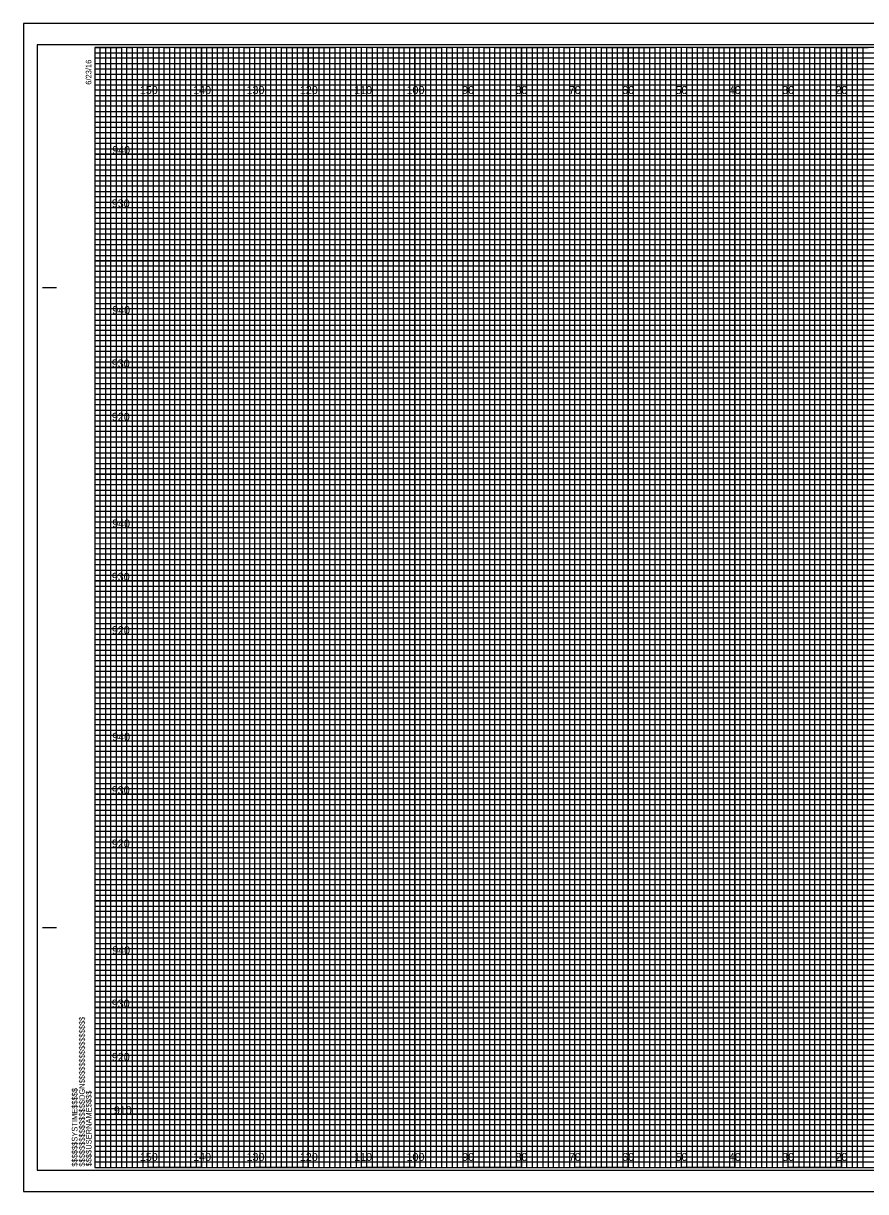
# Model space of a CAD drawing. Extents: x -13 to 323, y -4 to 214.
# Drawn here: x -13.4 to 144.5, y -4.5 to 214.5 of the extents above; entities that cross this region are included whole.
import ezdxf

# ---------------------------------------------------------------- set-up
doc = ezdxf.new("R2010")
doc.units = 0
for name, color, linetype in [('Prop XS Elevation Labels', 7, 'Continuous'), ('Prop XS Offset Labels', 7, 'Continuous'), ('Sheet Cross Section CELL', 7, 'Continuous'), ('Sheet Cross Section Grid Major CELL', 7, 'Continuous'), ('Sheet Cross Section Grid Middle CELL', 7, 'Continuous'), ('Sheet Cross Section Grid Minor 1 CELL', 7, 'Continuous'), ('Sheet Cross Section Grid Minor 2 CELL', 7, 'Continuous'), ('Sheet Cutting Line CELL', 7, 'Continuous'), ('Sheet DOT Grid CELL', 7, 'Continuous'), ('Sheet Plot Border Inside CELL', 7, 'Continuous'), ('Sheet Plot Border Outside CELL', 7, 'Continuous')]:
    doc.layers.add(name, color=color, linetype=linetype)

msp = doc.modelspace()

# ---------------------------------------------------------------- linework, layer by layer
at = {"layer": 'Sheet Cross Section CELL'}
for p, q in [((-9.8, 165), (-7.3, 165)), ((-9.7, 165), (-7.2, 165)), ((-9.8, 45), (-7.3, 45)), ((-9.7, 45), (-7.2, 45)), ((0, 0), (0, 0)), ((0, 0), (0, 0)), ((0, 0), (0, 0)), ((0, 0), (0, 0)), ((0, 0), (0, 0)), ((0, 0), (0, 0)), ((0, 0), (0, 0))]:
    msp.add_line(p, q, dxfattribs=at)
msp.add_lwpolyline([(320, 210), (0, 210), (0, 0), (320, 0)], close=True, dxfattribs=at)
at = {"layer": 'Sheet Cross Section Grid Major CELL'}
for p, q in [((10, 210), (0, 210)), ((10, 0), (10, 210)), ((30, 210), (20, 210)), ((20, 210), (20, 0)), ((30, 0), (30, 210)), ((50, 210), (40, 210)), ((40, 210), (40, 0)), ((50, 0), (50, 210)), ((70, 210), (60, 210)), ((60, 210), (60, 0)), ((70, 0), (70, 210)), ((90, 210), (80, 210)), ((80, 210), (80, 0)), ((90, 0), (90, 210)), ((110, 210), (100, 210)), ((100, 210), (100, 0)), ((110, 0), (110, 210)), ((130, 210), (120, 210)), ((120, 210), (120, 0)), ((130, 0), (130, 210)), ((150, 210), (140, 210)), ((140, 210), (140, 0)), ((20, 0), (10, 0)), ((40, 0), (30, 0)), ((60, 0), (50, 0)), ((80, 0), (70, 0)), ((100, 0), (90, 0)), ((120, 0), (110, 0)), ((140, 0), (130, 0))]:
    msp.add_line(p, q, dxfattribs=at)
for points in [[(0, 200), (320, 200), (320, 190), (0, 190)], [(0, 180), (320, 180), (320, 170), (0, 170)], [(0, 160), (320, 160), (320, 150), (0, 150)], [(0, 140), (320, 140), (320, 130), (0, 130)], [(0, 120), (320, 120), (320, 110), (0, 110)], [(0, 100), (320, 100), (320, 90), (0, 90)], [(0, 80), (320, 80), (320, 70), (0, 70)], [(0, 60), (320, 60), (320, 50), (0, 50)], [(0, 40), (320, 40), (320, 30), (0, 30)], [(0, 20), (320, 20), (320, 10), (0, 10)]]:
    msp.add_lwpolyline(points, dxfattribs=at)
at = {"layer": 'Sheet Cross Section Grid Middle CELL'}
for points in [[(0, 210), (5, 210), (5, 0), (15, 0), (15, 210), (25, 210), (25, 0), (35, 0), (35, 210), (45, 210), (45, 0), (55, 0), (55, 210), (65, 210), (65, 0), (75, 0), (75, 210), (85, 210), (85, 0), (95, 0), (95, 210), (105, 210), (105, 0), (115, 0), (115, 210), (125, 210), (125, 0), (135, 0), (135, 210), (145, 210)], [(0, 205), (275, 205)], [(0, 185), (320, 185), (320, 195), (0, 195)], [(0, 165), (320, 165), (320, 175), (0, 175)], [(0, 145), (320, 145), (320, 155), (0, 155)], [(0, 125), (320, 125), (320, 135), (0, 135)], [(0, 105), (320, 105), (320, 115), (0, 115)], [(0, 85), (320, 85), (320, 95), (0, 95)], [(0, 65), (320, 65), (320, 75), (0, 75)], [(0, 45), (320, 45), (320, 55), (0, 55)], [(0, 25), (320, 25), (320, 35), (0, 35)], [(0, 5), (320, 5), (320, 15), (0, 15)]]:
    msp.add_lwpolyline(points, dxfattribs=at)
at = {"layer": 'Sheet Cross Section Grid Minor 1 CELL'}
for p, q in [((0, 209), (260, 209)), ((260, 207.98), (0, 207.98)), ((0, 207.98), (0, 207)), ((0, 207), (260, 207)), ((260, 205.89), (0, 205.89)), ((0, 205.89), (0, 204)), ((0, 204), (320, 204))]:
    msp.add_line(p, q, dxfattribs=at)
for points in [[(0, 203), (270, 203), (320, 203), (320, 202), (0, 202)], [(0, 201), (320, 201), (320, 199), (0, 199)], [(0, 198), (320, 198), (320, 197), (0, 196.98)], [(0, 196), (320, 196), (320, 194), (0, 194)], [(0, 193), (320, 193), (320, 192), (0, 192)], [(0, 191), (320, 191), (320, 189), (0, 189)], [(0, 188), (320, 188), (320, 187), (0, 187)], [(0, 186), (320, 186), (320, 184), (0, 184)], [(0, 183), (320, 183), (320, 182), (0, 182)], [(0, 181), (320, 181), (320, 179), (0, 179)], [(0, 178), (320, 178), (320, 177), (0, 177)], [(0, 176), (320, 176), (320, 173.95), (320, 173), (320, 172), (0, 172)], [(0, 174), (320, 174), (320, 173), (0, 173)], [(0, 171), (320, 171), (320, 169), (0, 169.03)], [(0, 169.03), (320, 169), (320, 168), (0, 168)], [(0, 167), (320, 167), (320, 166), (0, 166)], [(0, 164), (320, 164), (320, 163), (0, 163)], [(0, 162), (320, 162), (320, 161), (0, 161)], [(-0.07, 158.89), (320, 158.89), (320, 157.88), (-0.07, 157.88)], [(0, 157), (320, 157), (320, 156), (0, 156)], [(0, 154), (320, 154), (320, 153), (0, 153)], [(0, 152), (320, 152), (320, 151), (0, 151)], [(0, 149), (320, 149), (320, 148), (0, 148)], [(0, 147), (320, 147), (320, 146), (0, 146)], [(0, 144), (320, 144), (320, 143), (0, 143)], [(0, 142), (320, 142), (320, 141), (0, 141)], [(0, 139), (320, 139), (319.99, 137.98), (0, 138)], [(0, 137), (320, 137), (320, 136), (0, 136)], [(0, 134), (320, 134), (320, 133), (0, 133)], [(0, 132), (320, 132), (320, 131), (0, 131)], [(0, 129), (320, 129), (320, 128), (0, 128)], [(0, 127), (320, 127), (320, 126), (0, 126)], [(0, 124), (320, 124), (320, 123), (0, 123)], [(0, 122), (320, 122), (320, 121), (0, 121)], [(0, 119), (320, 119), (320, 118), (0, 118)], [(0, 116.99), (320.07, 116.91), (320, 116), (0, 116)], [(0, 114), (320, 114), (320, 113), (0, 113)], [(0, 112), (320, 112), (320, 111), (0, 111)], [(0, 109), (320, 109), (320, 108), (0, 108)], [(0, 107), (320, 107), (320, 106), (0, 106)], [(0, 104), (320, 104), (320, 103), (0, 103)], [(0, 102), (320, 102), (320, 101), (0, 101)], [(0, 99), (320, 99), (320, 98), (0, 98)], [(0, 97), (320, 97), (320, 96), (0, 96)], [(0, 94), (320, 94), (320, 93), (0, 93)], [(0, 92), (320, 92), (320, 91), (0, 91)], [(0, 89), (320, 89), (320, 88), (0, 88)], [(0, 87), (320, 87), (320, 86), (0, 86)], [(0, 84), (320, 84), (320, 83), (0, 83)], [(0, 82), (320, 82), (320, 81), (0, 81)], [(0, 79), (320, 79), (319.99, 77.98), (0, 78)], [(0, 77), (320, 77), (320, 76), (0, 76)], [(0, 74), (320, 74), (320, 73), (0, 73)], [(0, 72), (320, 72), (320, 71), (0, 71)], [(0, 69), (320, 69), (320, 68), (0, 68)], [(0, 67), (320, 67), (320, 66), (0, 66)], [(0, 64), (320, 64), (320, 63), (0, 63)], [(0, 62), (320, 62), (320, 61), (0, 61)], [(0, 59), (320, 59), (320, 58), (0, 58)], [(0, 56.99), (320.07, 56.91), (320, 56), (0, 56)], [(0, 54), (320, 54), (320, 53), (0, 53)], [(0, 52), (320, 52), (320, 51), (0, 51)], [(0, 49), (320, 49), (320, 48), (0, 48)], [(0, 47), (320, 47), (320, 46), (0, 46)], [(0, 44), (320, 44), (320, 43), (0, 43)], [(0, 42), (320, 42), (320, 41), (0, 41)], [(0, 39), (320, 39), (320, 38), (0, 38)], [(0, 37), (320, 37), (320, 36), (0, 36)], [(0, 34), (320, 34), (320, 33), (0, 33)], [(0, 32), (320, 32), (320, 31), (0, 31)], [(0, 29), (320, 29), (320, 28), (0, 28)], [(0, 27), (320, 27), (320, 26), (0, 26)], [(0, 24), (320, 24), (320, 23), (0, 23)], [(0, 22), (320, 22), (320, 21), (0, 21)], [(0, 19), (320, 19), (320, 18), (0, 18)], [(0, 17), (320, 17), (320, 16), (0, 16)], [(0, 14), (320, 14), (320, 13), (0, 13)], [(0, 12), (320, 12), (320, 11), (0, 11)], [(0, 9), (320, 9), (320, 8), (0, 8)], [(0, 7), (320, 7), (320, 6), (0, 6)], [(0, 4), (320, 4), (320, 3), (0, 3)], [(0, 2), (320, 2), (320, 1), (0, 1)]]:
    msp.add_lwpolyline(points, dxfattribs=at)
at = {"layer": 'Sheet Cross Section Grid Minor 2 CELL'}
for points in [[(0, 0), (1, 0), (1, 210), (2, 210), (2, 0)], [(2, 0), (3, 0), (3, 210), (4, 210), (4, 0)], [(5, 0), (6, 0), (6, 210), (7, 210), (7, 0)], [(7, 0), (8, 0), (8, 210), (9, 210), (9, 0)], [(10, 0), (11, 0), (11, 210), (12, 210), (12, 0)], [(12, 0), (13, 0), (13, 210), (14, 210), (14, 0)], [(15, 0), (16, 0), (16, 210), (17, 210), (17, 0)], [(17, 0), (18, 0), (18, 210), (19, 210), (19, 0)], [(20, 0), (21, 0), (21, 210), (22, 210), (22, 0)], [(22, 0), (23, 0), (23, 210), (24, 210), (24, 0)], [(25, 0), (26, 0), (26, 210), (27, 210), (27, 0)], [(27, 0), (28, 0), (28, 210), (29, 210), (29, 0)], [(30, 0), (31, 0), (31, 210), (32, 210), (32, 0)], [(32, 0), (33, 0), (33, 210), (34, 210), (34, 0)], [(35, 0), (36, 0), (36, 210), (37, 210), (37, 0)], [(37, 0), (38, 0), (38, 210), (39, 210), (39, 0)], [(40, 0), (41, 0), (41, 210), (42, 210), (42, 0)], [(42, 0), (43, 0), (43, 210), (44, 210), (44, 0)], [(45, 0), (46, 0), (46, 210), (47, 210), (47, 0)], [(47, 0), (48, 0), (48, 210), (49, 210), (49, 0)], [(50, 0), (51, 0), (51, 210), (52, 210), (52, 0)], [(52, 0), (53, 0), (53, 210), (54, 210), (54, 0)], [(55, 0), (56, 0), (56, 210), (57, 210), (57, 0)], [(57, 0), (58, 0), (58, 210), (59, 210), (59, 0)], [(60, 0), (61, 0), (61, 210), (62, 210), (62, 0)], [(62, 0), (63, 0), (63, 210), (64, 210), (64, 0)], [(65, 0), (66, 0), (66, 210), (67, 210), (67, 0)], [(67, 0), (68, 0), (68, 210), (69, 210), (69, 0)], [(70, 0), (71, 0), (71, 210), (72, 210), (72, 0)], [(72, 0), (73, 0), (73, 210), (74, 210), (74, 0)], [(75, 0), (76, 0), (76, 210), (77, 210), (77, 0)], [(77, 0), (78, 0), (78, 210), (79, 210), (79, 0)], [(80, 0), (81, 0), (81, 210), (82, 210), (82, 0)], [(82, 0), (83, 0), (83, 210), (84, 210), (84, 0)], [(85, 0), (86, 0), (86, 210), (87, 210), (87, 0)], [(87, 0), (88, 0), (88, 210), (89, 210), (89, 0)], [(90, 0), (91, 0), (91, 210), (92, 210), (92, 0)], [(92, 0), (93, 0), (93, 210), (94, 210), (94, 0)], [(95, 0), (96, 0), (96, 210), (97, 210), (97, 0)], [(97, 0), (98, 0), (98, 210), (99, 210), (99, 0)], [(100, 0), (101, 0), (101, 210), (102, 210), (102, 0)], [(102, 0), (103, 0), (103, 210), (104, 210), (104, 0)], [(105, 0), (106, 0), (106, 210), (107, 210), (107, 0)], [(107, 0), (108, 0), (108, 210), (109, 210), (109, 0)], [(110, 0), (111, 0), (111, 210), (112, 210), (112, 0)], [(112, 0), (113, 0), (113, 210), (114, 210), (114, 0)], [(115, 0), (116, 0), (116, 210), (117, 210), (117, 0)], [(117, 0), (118, 0), (118, 210), (119, 210), (119, 0)], [(120, 0), (121, 0), (121, 210), (122, 210), (122, 0)], [(122, 0), (123, 0), (123, 210), (124, 210), (124, 0)], [(125, 0), (126, 0), (126, 210), (127, 210), (127, 0)], [(127, 0), (128, 0), (128, 210), (129, 210), (129, 0)], [(130, 0), (131, 0), (131, 210), (132, 210), (132, 0)], [(132, 0), (133, 0), (133, 210), (134, 210), (134, 0)], [(135, 0), (136, 0), (136, 210), (137, 210), (137, 0)], [(137, 0), (138, 0), (138, 210), (139, 210), (139, 0)], [(140, 0), (141, 0), (141, 210), (142, 210), (142, 0)], [(142, 0), (143, 0), (143, 210), (144, 210), (144, 0)]]:
    msp.add_lwpolyline(points, dxfattribs=at)
at = {"layer": 'Sheet Cutting Line CELL'}
for p, q in [((323.3, 214.5), (-13.4, 214.5)), ((-13.4, 214.5), (-13.4, -4.5)), ((-13.4, -4.5), (323.3, -4.5))]:
    msp.add_line(p, q, dxfattribs=at)
at = {"layer": 'Sheet DOT Grid CELL'}
for p, q in [((10, 0), (10, 210)), ((20, 0), (20, 210)), ((30, 0), (30, 210)), ((40, 0), (40, 210)), ((50, 0), (50, 210)), ((60, 0), (60, 210)), ((70, 0), (70, 210)), ((80, 0), (80, 210)), ((90, 0), (90, 210)), ((100, 0), (100, 210)), ((110, 0), (110, 210)), ((120, 0), (120, 210)), ((130, 0), (130, 210)), ((140, 0), (140, 210)), ((0, 200), (320, 200)), ((0, 190), (320, 190)), ((0, 180), (320, 180)), ((0, 170), (320, 170)), ((0, 160), (320, 160)), ((0, 150), (320, 150)), ((0, 140), (320, 140)), ((0, 130), (320, 130)), ((0, 120), (320, 120)), ((0, 110), (320, 110)), ((0, 100), (320, 100)), ((0, 90), (320, 90)), ((0, 80), (320, 80)), ((0, 70), (320, 70)), ((0, 60), (320, 60)), ((0, 50), (320, 50)), ((0, 40), (320, 40)), ((0, 30), (320, 30)), ((0, 20), (320, 20)), ((0, 10), (320, 10))]:
    msp.add_line(p, q, dxfattribs=at)
at = {"layer": 'Sheet Plot Border Inside CELL'}
msp.add_lwpolyline([(-10.8, -0.5), (322.4, -0.5), (322.4, 210.5), (-10.8, 210.5)], close=True, dxfattribs=at)
at = {"layer": 'Sheet Plot Border Outside CELL'}
msp.add_lwpolyline([(-13.4, -4.5), (323.3, -4.5), (323.3, 214.5), (-13.4, 214.5)], close=True, dxfattribs=at)

# ---------------------------------------------------------------- texts
at = {"layer": 'Prop XS Elevation Labels'}
for s, p in [('940', (3.26, 190)), ('930', (3.18, 180)), ('940', (3.26, 160)), ('930', (3.18, 150)), ('920', (3.19, 140)), ('940', (3.26, 120)), ('930', (3.18, 110)), ('920', (3.19, 100)), ('940', (3.26, 80)), ('930', (3.18, 70)), ('920', (3.19, 60)), ('940', (3.26, 40)), ('930', (3.18, 30)), ('920', (3.19, 20)), ('910', (3.57, 10))]:
    msp.add_text(s, height=1.5, dxfattribs=at).set_placement(p)
at = {"layer": 'Prop XS Offset Labels'}
for s, p in [('150', (8.44, 201.25)), ('140', (18.44, 201.25)), ('130', (28.44, 201.25)), ('120', (38.44, 201.25)), ('110', (48.62, 201.25)), ('100', (58.44, 201.25)), ('90', (68.86, 201.25)), ('80', (78.86, 201.25)), ('70', (88.86, 201.25)), ('60', (98.86, 201.25)), ('50', (108.86, 201.25)), ('40', (118.86, 201.25)), ('30', (128.86, 201.25)), ('20', (138.86, 201.25)), ('150', (8.44, 1.25)), ('140', (18.44, 1.25)), ('130', (28.44, 1.25)), ('120', (38.44, 1.25)), ('110', (48.62, 1.25)), ('100', (58.44, 1.25)), ('90', (68.86, 1.25)), ('80', (78.86, 1.25)), ('70', (88.86, 1.25)), ('60', (98.86, 1.25)), ('50', (108.86, 1.25)), ('40', (118.86, 1.25)), ('30', (128.86, 1.25)), ('20', (138.86, 1.25))]:
    msp.add_text(s, height=1.5, dxfattribs=at).set_placement(p)
at = {"layer": 'Sheet Cross Section CELL'}
for s, p in [('6/23/16', (-0.65, 203)), ('$$$$$$$$$$$$$$$$DGN$$$$$$$$$$$$$$$$', (-1.88, 0.18)), ('$$$$$$SYSTIME$$$$$', (-3.26, 0.18)), ('$$$$USERNAME$$$$', (-0.62, 0.23))]:
    msp.add_text(s, height=1.05, rotation=90, dxfattribs=at).set_placement(p)

doc.saveas('drawing.dxf')
